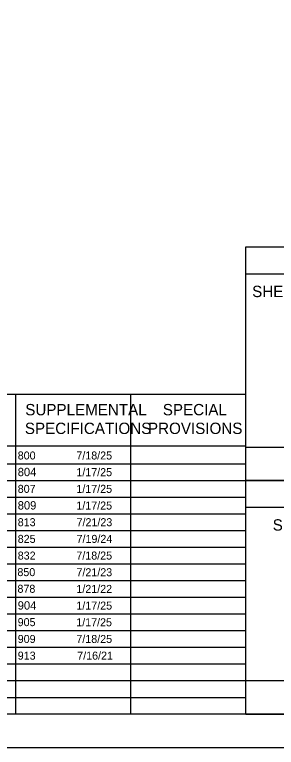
# Model space of a CAD drawing. Extents: x -21.9 to 47.3, y 14.1 to 48.7.
# Drawn here: x 20.13 to 24.06, y 26.73 to 37.72 of the extents above; entities that cross this region are included whole.
import ezdxf

# ---------------------------------------------------------------- set-up
doc = ezdxf.new("R2010")
doc.units = 0
for name, color, linetype in [('GM_X_City_Street', 7, 'Continuous'), ('SH_Border', 7, 'Continuous'), ('SH_Cut_Line', 7, 'Continuous'), ('SH_Data', 7, 'Continuous'), ('SH_Text', 7, 'Continuous')]:
    doc.layers.add(name, color=color, linetype=linetype)

msp = doc.modelspace()

# ---------------------------------------------------------------- linework, layer by layer
at = {"layer": 'SH_Border'}
msp.add_lwpolyline([(1.5, 48.233), (33.5, 48.233), (33.5, 27.233), (1.5, 27.233)], close=True, dxfattribs=at)
at = {"layer": 'SH_Cut_Line'}
msp.add_lwpolyline([(0, 26.733), (34, 26.733), (34, 48.733), (0, 48.733)], close=True, dxfattribs=at)
at = {"layer": 'SH_Data'}
for p, q in [((23.6, 30.733), (23.6, 34.233)), ((23.6, 34.233), (26.4, 34.233)), ((23.6, 33.833), (26.4, 33.833)), ((10.15, 32.025), (23.6, 32.025)), ((20.15, 27.233), (20.15, 32.025)), ((21.875, 27.233), (21.875, 32.025)), ((23.6, 27.233), (23.6, 32.025)), ((10.15, 31.254), (23.6, 31.254)), ((10.15, 30.983), (23.6, 30.983)), ((10.15, 30.733), (23.6, 30.733)), ((23.6, 30.733), (26.4, 30.733)), ((23.6, 27.233), (23.6, 30.733)), ((23.6, 30.733), (26.4, 30.733)), ((10.15, 30.483), (23.6, 30.483)), ((23.6, 30.333), (26.4, 30.333)), ((10.15, 30.233), (23.6, 30.233)), ((10.15, 29.983), (23.6, 29.983)), ((10.15, 29.733), (23.6, 29.733)), ((10.15, 29.483), (23.6, 29.483)), ((10.15, 29.233), (23.6, 29.233)), ((10.15, 28.983), (23.6, 28.983)), ((10.15, 28.733), (23.6, 28.733)), ((10.15, 28.483), (23.6, 28.483)), ((10.15, 28.233), (23.6, 28.233)), ((10.15, 27.983), (23.6, 27.983)), ((10.15, 27.733), (23.6, 27.733)), ((10.15, 27.483), (23.6, 27.483)), ((23.6, 27.233), (26.4, 27.233))]:
    msp.add_line(p, q, dxfattribs=at)
for points in [[(23.6, 30.733), (23.6, 31.233), (26.4, 31.233), (26.4, 30.733)], [(23.6, 27.233), (23.6, 27.733), (26.4, 27.733), (26.4, 27.233)]]:
    msp.add_lwpolyline(points, close=True, dxfattribs=at)

# ---------------------------------------------------------------- texts
at = {"layer": 'GM_X_City_Street'}
for s, height, p in [('804', 0.125, (20.18, 30.798)), ('809', 0.125, (20.18, 30.298)), ('850', 0.12, (20.175, 29.3)), ('7/21/23', 0.12, (21.06, 29.298)), ('878', 0.12, (20.176, 29.05)), ('1/21/22', 0.12, (21.059, 29.048)), ('904', 0.125, (20.18, 28.798)), ('905', 0.12, (20.179, 28.55)), ('1/17/25', 0.12, (21.057, 28.548))]:
    msp.add_text(s, height=height, dxfattribs=at).set_placement(p)
at = {"layer": 'SH_Text'}
for s, height, p in [('SHEETS: 1-21, 25, 27-86,', 0.17, (23.693, 33.482)), ('SUPPLEMENTAL', 0.17, (20.293, 31.71)), ('SPECIAL', 0.17, (22.354, 31.71)), ('SPECIFICATIONS', 0.17, (20.287, 31.43)), ('PROVISIONS', 0.17, (22.132, 31.43)), ('800     ', 0.12, (20.18, 31.048)), (' 7/18/25', 0.12, (21.014, 31.048)), (' 1/17/25', 0.12, (21.014, 30.798)), ('807', 0.12, (20.18, 30.548)), (' 1/17/25', 0.12, (21.014, 30.548)), (' 1/17/25', 0.12, (21.014, 30.298)), ('813     ', 0.12, (20.18, 30.048)), (' 7/21/23', 0.12, (21.017, 30.048)), ('SHEETS: 26, 87-89,', 0.17, (24.001, 29.982)), ('825     ', 0.12, (20.18, 29.798)), (' 7/19/24', 0.12, (21.017, 29.798)), ('832     ', 0.12, (20.18, 29.548)), (' 7/18/25', 0.12, (21.014, 29.548)), (' 1/17/25', 0.12, (21.014, 28.798)), ('909     ', 0.12, (20.18, 28.298)), (' 7/18/25', 0.12, (21.014, 28.298)), ('913     ', 0.12, (20.18, 28.048)), (' 7/16/21', 0.12, (21.027, 28.048))]:
    msp.add_text(s, height=height, dxfattribs=at).set_placement(p)

doc.saveas('drawing.dxf')
